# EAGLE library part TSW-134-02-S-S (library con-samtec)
THROUGH-HOLE .025" SQ POST HEADER Source: Samtec TSW.pdf
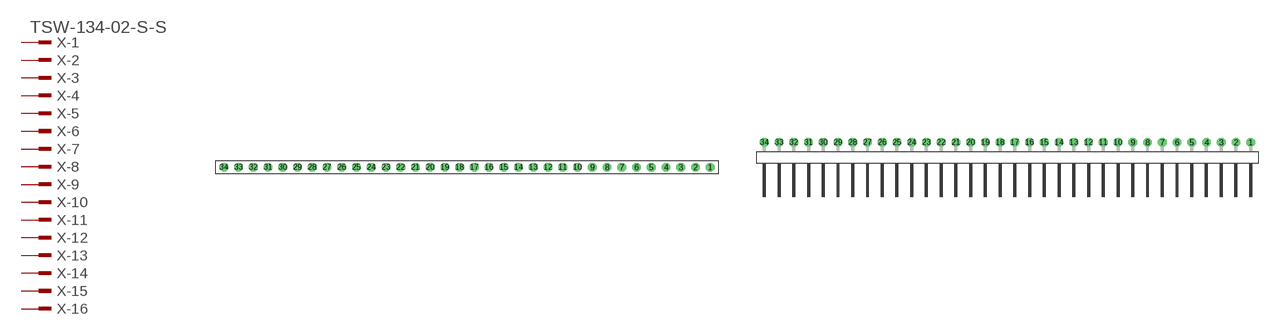
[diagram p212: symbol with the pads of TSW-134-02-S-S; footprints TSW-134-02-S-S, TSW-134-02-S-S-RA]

Designator prefix X; gates -1=MPINV -2=MPIN -3=MPIN -4=MPIN -5=MPIN -6=MPIN -7=MPIN -8=MPIN -9=MPIN -10=MPIN -11=MPIN -12=MPIN -13=MPIN -14=MPIN -15=MPIN -16=MPIN -17=MPIN -18=MPIN -19=MPIN -20=MPIN -21=MPIN -22=MPIN -23=MPIN -24=MPIN -25=MPIN -26=MPIN -27=MPIN -28=MPIN -29=MPIN -30=MPIN -31=MPIN -32=MPIN -33=MPIN -34=MPIN

## TSW-134-02-S-S (OC_FARNELL: unknown; OC_NEWARK: unknown)  [TSW-134-02-S-S]
1  -1:1  pas
2  -2:1  pas
3  -3:1  pas
4  -4:1  pas
5  -5:1  pas
6  -6:1  pas
7  -7:1  pas
8  -8:1  pas
9  -9:1  pas
10  -10:1  pas
11  -11:1  pas
12  -12:1  pas
13  -13:1  pas
14  -14:1  pas
15  -15:1  pas
16  -16:1  pas
17  -17:1  pas
18  -18:1  pas
19  -19:1  pas
20  -20:1  pas
21  -21:1  pas
22  -22:1  pas
23  -23:1  pas
24  -24:1  pas
25  -25:1  pas
26  -26:1  pas
27  -27:1  pas
28  -28:1  pas
29  -29:1  pas
30  -30:1  pas
31  -31:1  pas
32  -32:1  pas
33  -33:1  pas
34  -34:1  pas

## TSW-134-02-S-S-RA (OC_FARNELL: unknown; OC_NEWARK: unknown)  [TSW-134-02-S-S-RA]
Pads as for TSW-134-02-S-S

## Footprint TSW-134-02-S-S (pad centres in mm)
THROUGH-HOLE .025" SQ POST HEADER Source: Samtec TSW.pdf
drill 1 pad 1.5 octagon: 1 41.91,0; 2 39.37,0; 3 36.83,0; 4 34.29,0; 5 31.75,0; 6 29.21,0; 7 26.67,0; 8 24.13,0; 9 21.59,0; 10 19.05,0; 11 16.51,0; 12 13.97,0; 13 11.43,0; 14 8.89,0; 15 6.35,0; 16 3.81,0; 17 1.27,0; 18 -1.27,0; 19 -3.81,0; 20 -6.35,0; 21 -8.89,0; 22 -11.43,0; 23 -13.97,0; 24 -16.51,0; 25 -19.05,0; 26 -21.59,0; 27 -24.13,0; 28 -26.67,0; 29 -29.21,0; 30 -31.75,0; 31 -34.29,0; 32 -36.83,0; 33 -39.37,0; 34 -41.91,0

## Footprint TSW-134-02-S-S-RA (pad centres in mm)
THROUGH-HOLE .025" SQ POST HEADER Source: Samtec TSW.pdf
drill 1 pad 1.5 octagon: 1 41.91,1.524; 2 39.37,1.524; 3 36.83,1.524; 4 34.29,1.524; 5 31.75,1.524; 6 29.21,1.524; 7 26.67,1.524; 8 24.13,1.524; 9 21.59,1.524; 10 19.05,1.524; 11 16.51,1.524; 12 13.97,1.524; 13 11.43,1.524; 14 8.89,1.524; 15 6.35,1.524; 16 3.81,1.524; 17 1.27,1.524; 18 -1.27,1.524; 19 -3.81,1.524; 20 -6.35,1.524; 21 -8.89,1.524; 22 -11.43,1.524; 23 -13.97,1.524; 24 -16.51,1.524; 25 -19.05,1.524; 26 -21.59,1.524; 27 -24.13,1.524; 28 -26.67,1.524; 29 -29.21,1.524; 30 -31.75,1.524; 31 -34.29,1.524; 32 -36.83,1.524; 33 -39.37,1.524; 34 -41.91,1.524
